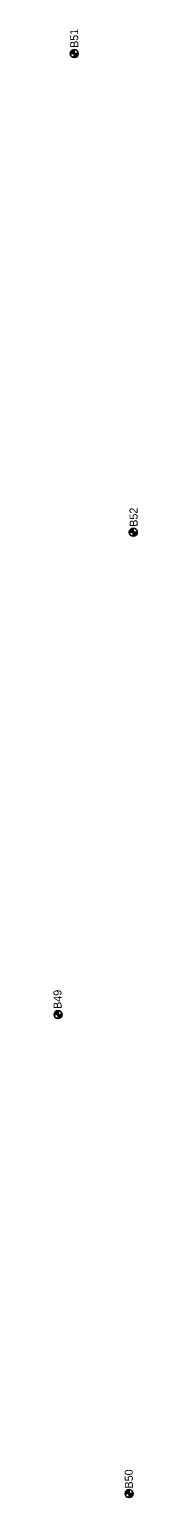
# Model space of a CAD drawing. Extents: x 331323 to 388339, y 121519 to 205315.
# Drawn here: x 360146 to 360251, y 156328 to 158162 of the extents above; entities that cross this region are included whole.
import ezdxf

# ---------------------------------------------------------------- set-up
doc = ezdxf.new("R2010")
doc.units = 0
for name, color, linetype in [('E_SOIL_BORE1 [KAPUR_CADDS_LEVELS]', 7, 'Continuous'), ('E_SOIL_BORE2 [KAPUR_CADDS_LEVELS]', 7, 'Continuous'), ('P_MARK', 7, 'Continuous')]:
    doc.layers.add(name, color=color, linetype=linetype)

msp = doc.modelspace()

# ---------------------------------------------------------------- linework, layer by layer
at = {"layer": 'P_MARK'}
for p, q in [((360166.9, 158132), (360176.9, 158132)), ((360171.9, 158137), (360171.9, 158127)), ((360240.6, 157534), (360250.6, 157534)), ((360245.6, 157539), (360245.6, 157529)), ((360151.6, 156936.2), (360151.6, 156926.2)), ((360146.6, 156931.2), (360156.6, 156931.2)), ((360235.4, 156332.7), (360245.4, 156332.7)), ((360240.4, 156337.7), (360240.4, 156327.7))]:
    msp.add_line(p, q, dxfattribs=at)
for centre in [(360171.9, 158132), (360245.6, 157534), (360151.6, 156931.2), (360240.4, 156332.7)]:
    msp.add_circle(centre, 5, dxfattribs=at)
for centre, radius, start, end in [((360171.9, 158132), 4.5, 89.9869, 179.9869), ((360171.9, 158132), 4, 89.9869, 179.9869), ((360171.9, 158132), 3.5, 89.9869, 179.9869), ((360171.9, 158132), 3, 89.9869, 179.9869), ((360171.9, 158132), 2.5, 89.9869, 179.9869), ((360171.9, 158132), 2, 89.9869, 179.9869), ((360171.9, 158132), 1.5, 89.9869, 179.9869), ((360171.9, 158132), 1, 89.9869, 179.9869), ((360171.9, 158132), 0.5, 89.9869, 179.9869), ((360171.9, 158132), 4.5, 269.9869, 359.9869), ((360171.9, 158132), 4, 269.9869, 359.9869), ((360171.9, 158132), 3.5, 269.9869, 359.9869), ((360171.9, 158132), 3, 269.9869, 359.9869), ((360171.9, 158132), 2.5, 269.9869, 359.9869), ((360171.9, 158132), 2, 269.9869, 359.9869), ((360171.9, 158132), 1.5, 269.9869, 359.9869), ((360171.9, 158132), 1, 269.9869, 359.9869), ((360171.9, 158132), 0.5, 269.9869, 359.9869), ((360245.6, 157534), 4.5, 89.9869, 179.9869), ((360245.6, 157534), 4, 89.9869, 179.9869), ((360245.6, 157534), 3.5, 89.9869, 179.9869), ((360245.6, 157534), 3, 89.9869, 179.9869), ((360245.6, 157534), 2.5, 89.9869, 179.9869), ((360245.6, 157534), 2, 89.9869, 179.9869), ((360245.6, 157534), 1.5, 89.9869, 179.9869), ((360245.6, 157534), 1, 89.9869, 179.9869), ((360245.6, 157534), 0.5, 89.9869, 179.9869), ((360245.6, 157534), 4.5, 269.9869, 359.9869), ((360245.6, 157534), 4, 269.9869, 359.9869), ((360245.6, 157534), 3.5, 269.9869, 359.9869), ((360245.6, 157534), 3, 269.9869, 359.9869), ((360245.6, 157534), 2.5, 269.9869, 359.9869), ((360245.6, 157534), 2, 269.9869, 359.9869), ((360245.6, 157534), 1.5, 269.9869, 359.9869), ((360245.6, 157534), 1, 269.9869, 359.9869), ((360245.6, 157534), 0.5, 269.9869, 359.9869), ((360151.6, 156931.2), 4.5, 89.9869, 179.9869), ((360151.6, 156931.2), 4, 89.9869, 179.9869), ((360151.6, 156931.2), 3.5, 89.9869, 179.9869), ((360151.6, 156931.2), 3, 89.9869, 179.9869), ((360151.6, 156931.2), 2.5, 89.9869, 179.9869), ((360151.6, 156931.2), 2, 89.9869, 179.9869), ((360151.6, 156931.2), 1.5, 89.9869, 179.9869), ((360151.6, 156931.2), 1, 89.9869, 179.9869), ((360151.6, 156931.2), 0.5, 89.9869, 179.9869), ((360151.6, 156931.2), 4.5, 269.9869, 359.9869), ((360151.6, 156931.2), 4, 269.9869, 359.9869), ((360151.6, 156931.2), 3.5, 269.9869, 359.9869), ((360151.6, 156931.2), 3, 269.9869, 359.9869), ((360151.6, 156931.2), 2.5, 269.9869, 359.9869), ((360151.6, 156931.2), 2, 269.9869, 359.9869), ((360151.6, 156931.2), 1.5, 269.9869, 359.9869), ((360151.6, 156931.2), 1, 269.9869, 359.9869), ((360151.6, 156931.2), 0.5, 269.9869, 359.9869), ((360240.4, 156332.7), 4.5, 89.9869, 179.9869), ((360240.4, 156332.7), 4, 89.9869, 179.9869), ((360240.4, 156332.7), 3.5, 89.9869, 179.9869), ((360240.4, 156332.7), 3, 89.9869, 179.9869), ((360240.4, 156332.7), 2.5, 89.9869, 179.9869), ((360240.4, 156332.7), 2, 89.9869, 179.9869), ((360240.4, 156332.7), 1.5, 89.9869, 179.9869), ((360240.4, 156332.7), 1, 89.9869, 179.9869), ((360240.4, 156332.7), 0.5, 89.9869, 179.9869), ((360240.4, 156332.7), 4.5, 269.9869, 359.9869), ((360240.4, 156332.7), 4, 269.9869, 359.9869), ((360240.4, 156332.7), 3.5, 269.9869, 359.9869), ((360240.4, 156332.7), 3, 269.9869, 359.9869), ((360240.4, 156332.7), 2.5, 269.9869, 359.9869), ((360240.4, 156332.7), 2, 269.9869, 359.9869), ((360240.4, 156332.7), 1.5, 269.9869, 359.9869), ((360240.4, 156332.7), 1, 269.9869, 359.9869), ((360240.4, 156332.7), 0.5, 269.9869, 359.9869)]:
    msp.add_arc(centre, radius, start, end, dxfattribs=at)

# ---------------------------------------------------------------- texts
at = {"layer": 'E_SOIL_BORE1 [KAPUR_CADDS_LEVELS]'}
msp.add_text('B50', height=10, rotation=90.6368, dxfattribs=at).set_placement((360245.1, 156339.2))
at = {"layer": 'E_SOIL_BORE2 [KAPUR_CADDS_LEVELS]'}
for s, p in [('B51', (360176.9, 158139.2)), ('B52', (360251.1, 157540.9)), ('B49', (360156.1, 156938.4))]:
    msp.add_text(s, height=10, rotation=90.6368, dxfattribs=at).set_placement(p)

doc.saveas('drawing.dxf')
